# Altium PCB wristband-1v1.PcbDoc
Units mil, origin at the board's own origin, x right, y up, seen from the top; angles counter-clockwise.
Board outline 1555.12 x 610.86 mil, 4 copper layers (Top Layer, Layer 1, Layer 2, Bottom Layer), stack 23.78 mil thick; 50 components, 63 nets, 221 pads, 110 vias.
Unrouted connection lines stored in the file: 30.
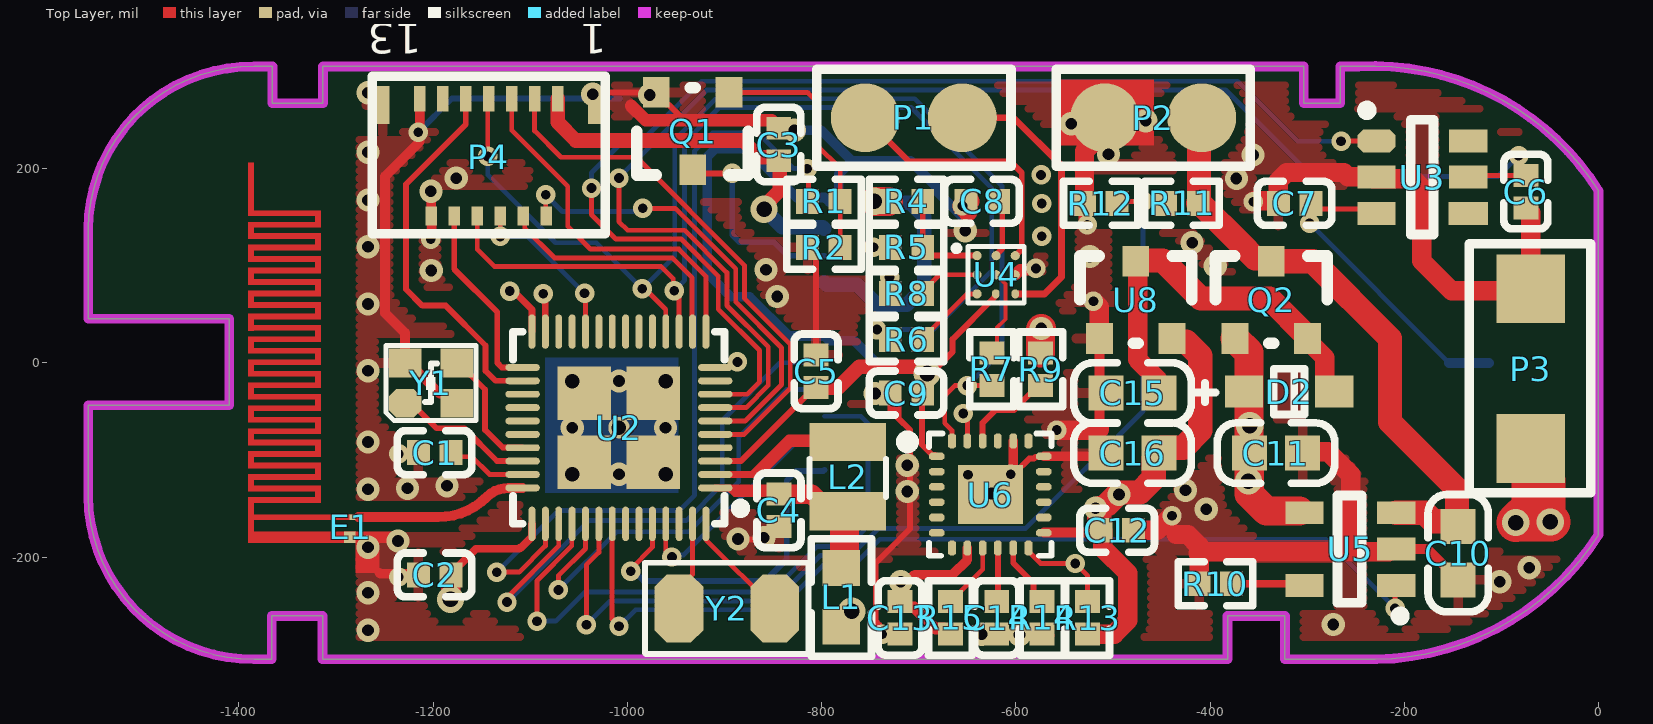
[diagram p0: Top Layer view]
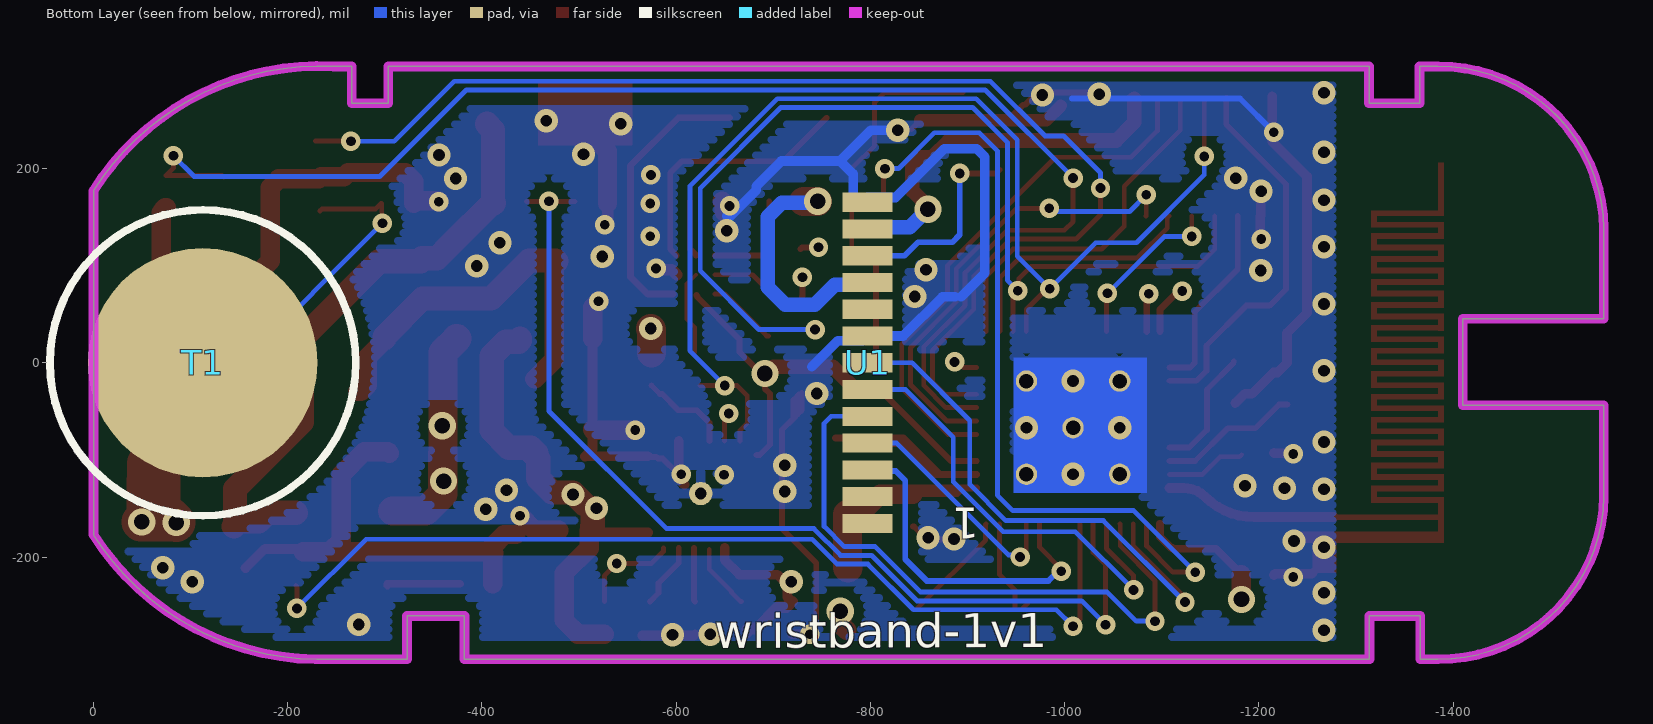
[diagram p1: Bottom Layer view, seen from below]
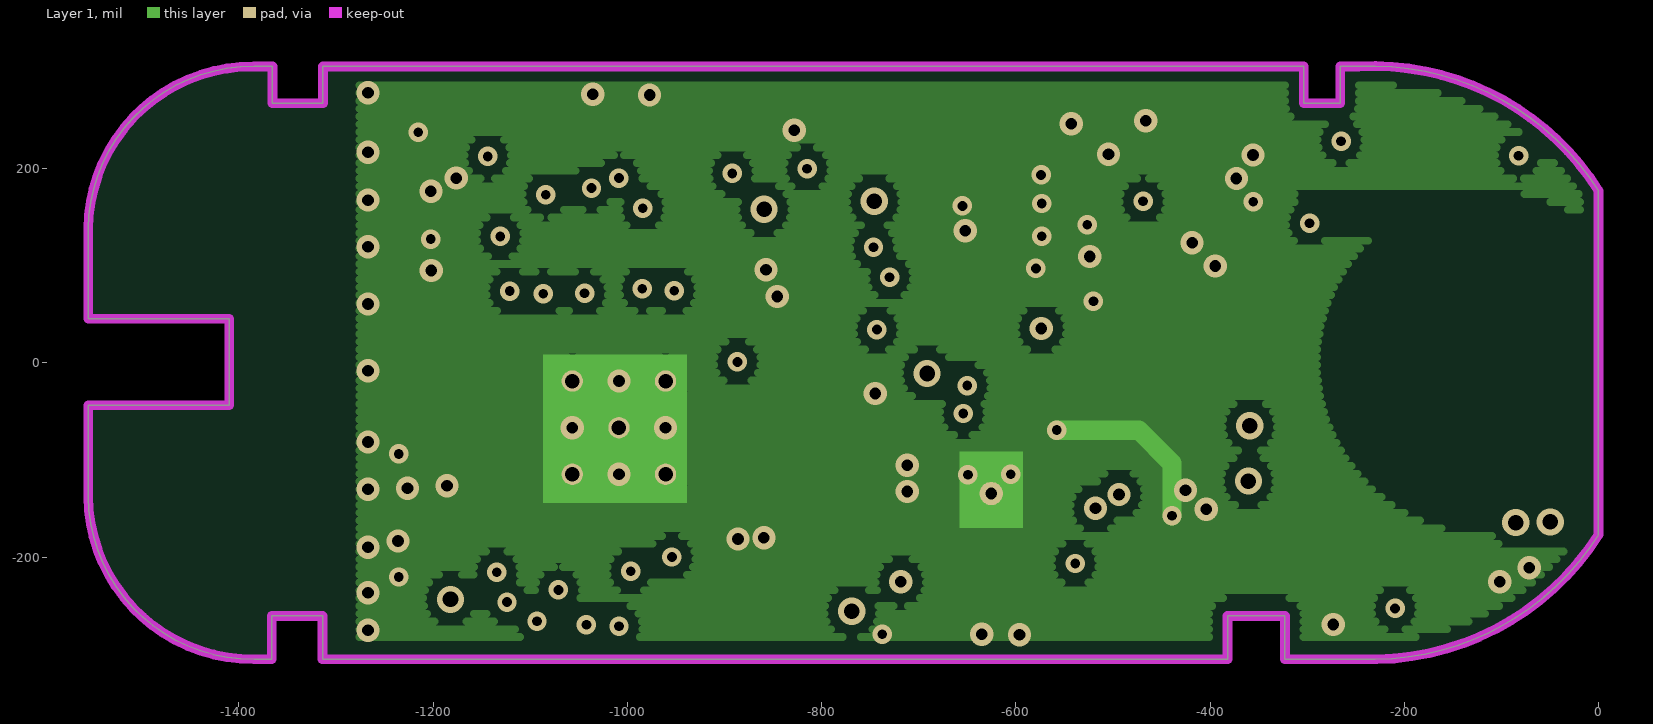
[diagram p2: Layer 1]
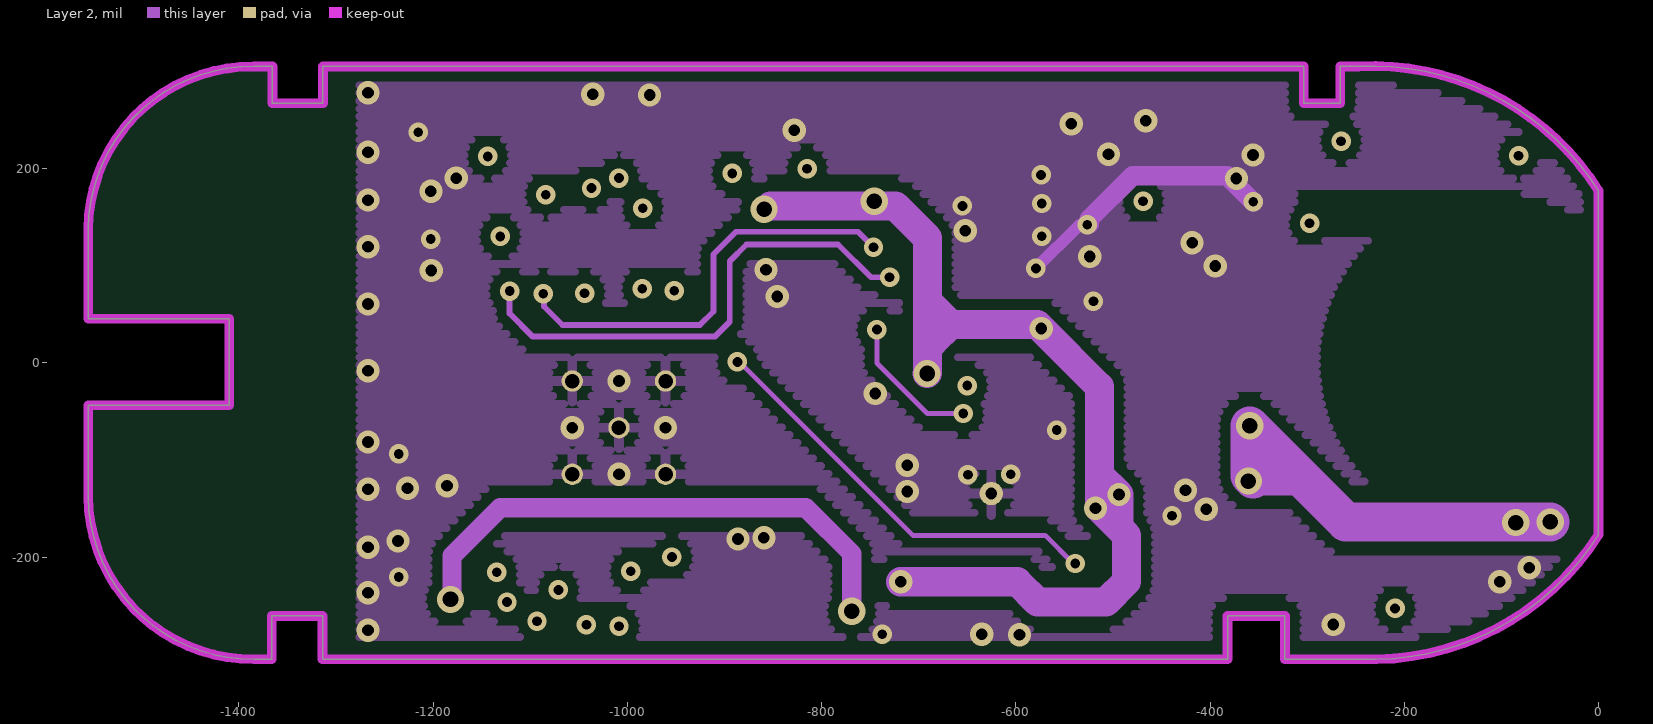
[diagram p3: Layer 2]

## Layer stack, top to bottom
Top Solder: solder mask 0.3937, Solder Resist, Dk 3.5
Top Layer: signal copper 1.4173
Dielectric 2: prepreg 2.7953, PP-006, Dk 4.1
Layer 1: signal copper 1.378
Dielectric 3: prepreg 2.7953, PP-006, Dk 4.1
Layer 2: signal copper 1.378
Dielectric 1: dielectric 12.5984, FR-4, Dk 4.8
Bottom Layer: signal copper 1.4173
Bottom Solder: solder mask 0.3937, Solder Resist, Dk 3.5

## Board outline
-1555.12,-137.8 ccw(c-1386.04,-136.02) -1384.27,-305.1 -1384.27,-305.12 -1366.14,-305.12 -1366.14,-260.71 -1313.78,-260.71 -1313.78,-305.12 -381.89,-305.12 -381.89,-260.71 -322.83,-260.71 -322.83,-305.12 -246.85,-305.12 -246.84,-305.1 ccw(c-233.14,-29.47) 0,-177.15 0,177.17 ccw(c-233.14,29.48) -246.84,305.12 -265.75,305.12 -265.75,267.34 -303.54,267.34 -303.54,305.12 -1313.39,305.12 -1313.39,267.34 -1365.35,267.34 -1365.35,305.12 -1384.27,305.12 ccw(c-1386.03,136.03) -1555.12,137.8 -1555.12,45.28 -1409.98,45.28 -1409.98,-43.7 -1555.12,-43.7

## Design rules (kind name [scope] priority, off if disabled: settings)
Clearance Clearance_2 [InNamedPolygon('GND1')] p1: gap=6 ignorepadtopadclearanceinfootprint=FALSE
Clearance Clearance_1 [InPolygon] p2: gap=10 ignorepadtopadclearanceinfootprint=FALSE
Clearance [All] p3: gap=6 ignorepadtopadclearanceinfootprint=FALSE except(3.5: Arc-SMDPad Track-SMDPad; 4: Arc-Arc Arc-Track Track-Track SMDPad-SMDPad)
ComponentClearance [All] p1 off: gap=10 collisioncheckmode=3 verticalgap=10 showdistances=FALSE
DiffPairsRouting [All] p1: maxlimit=10 minlimit=7 mostfreqgap=8 toplayer_minwidth=6 toplayer_maxwidth=15 toplayer_prefwidth=8 midlayer1_minwidth=6 midlayer1_maxwidth=15 midlayer1_prefwidth=8 midlayer2_minwidth=6 midlayer2_maxwidth=15 midlayer2_prefwidth=8 bottomlayer_minwidth=6 bottomlayer_maxwidth=15 bottomlayer_prefwidth=8 maxuncoupledlength=500
MinimumSolderMaskSliver [All] p1 off: minsoldermaskwidth=10
PolygonConnect PolygonConnect_1 [IsVia] p1: connectstyle=Direct reliefconductorwidth=10 reliefentries=4 polygonreliefangle="90 Angle" airgapwidth=10
PolygonConnect [All] p2: connectstyle=Relief reliefconductorwidth=10 reliefentries=4 polygonreliefangle="90 Angle" airgapwidth=10
RoutingVias [All] p1: holewidth=16 width=28 viastyle="Through Hole" minholewidth=10 minwidth=20 maxholewidth=28 maxwidth=50
SilkToSilkClearance [All] p1 off: silktosilkclearance=10
SilkToSolderMaskClearance [IsPad] p1 off: minsilkscreentomaskgap=10 clearancetoexposedcopper=TRUE
SolderMaskExpansion [All] p1: expansion=4 istentingtop=FALSE
Width [All] p1: maxlimit=100 minlimit=3.5 preferedwidth=10
25 further rules are at their usual default settings.

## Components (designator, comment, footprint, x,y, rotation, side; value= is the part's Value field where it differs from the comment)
C1 "1uF" 0402_C -1181.7,-92.5 r270 top
C2 "0.1uF" 0402_C -1181.7,-218.43 r270 top
C3 "1uF" 0402_C -843.97,208.02 r180 top
C4 "2.2uF" 0402_C -843.81,-168.66 r180 top
C5 "2.2uF" 0402_C -805.63,7.94 r0 top
C6 "NC" 0402_C -74.78,193.01 r0 top
C7 "10pF" 0402_C -296.14,164.16 r270 top
C8 "1uF" 0402_C -651.46,166.26 r90 top
C9 "0.1uF" 0402_C -729.26,-31.15 r90 top
C10 "10uF" 0603_C -144.51,-223.51 r90 top
C11 "10uF" 0603_C -304.56,-93 r180 top
C12 "0.1uF" 0402_C -478.86,-172.36 r270 top
C13 "0.1uF" 0402_C -719.12,-279.37 r180 top
C14 "0.1uF" 0402_C -619.54,-245.9 r0 top
C15 "10uF" 0603_C -452.3,-31.06 r180 top
C16 "10uF" 0603_C -452.3,-93 r180 top
D2 "Diode" SOD-323 -364.97,-29.58 r0 top
E1 "ANTENNA" ANT-F-1-2.4G-0.8 -1283.04,-158.93 r90 top
L1 "0Ω" 0603 -779.61,-211.26 r270 top
L2 "22uH" SMD_2x2mm -772.88,-117.13 r270 top
P1 "0827马达" SIP2-2.54mm#1 -755,252.33 r90 top
P2 "锂电池（圆形焊盘）" SIP2-2.54mm#1 -408.43,252.33 r270 top
P3 "电源(矩形焊盘)" SIP2-2.54mm#2 -55.59,-51.12 r180 top
P4 "FPC连接器 13PIN_0.3mm" FFC/FPC-13(6+7)-P0.3 -1142.66,271.98 r180 top
Q1 "QNPN" SOT-23 -895.29,278.38 r180 top
Q2 "MOSFET-P" SOT-23 -374.38,24.97 r0 top
R1 "1K" 0402 -780.77,166.26 r180 top
R2 "10K" 0402 -780.77,118.84 r180 top
R4 "0R" 0402 -729.26,166.26 r0 top
R5 "10K" 0402 -729.26,118.84 r0 top
R6 "0R" 0402 -729.26,24.01 r0 top
R7 "0R" 0402 -624.61,-23.41 r90 top
R8 "0R" 0402 -729.26,71.43 r0 top
R9 "10K" 0402 -574.41,-23.41 r90 top
R10 "100K" 0402 -377.71,-227.48 r180 top
R11 "100K" 0402 -412.1,164.16 r180 top
R12 "100K" 0402 -529.23,164.16 r0 top
R13 "10K" 0402 -526.08,-245.9 r270 top
R14 "10K" 0402 -572.81,-245.9 r270 top
R15 "10K" 0402 -667.27,-245.9 r270 top
T1 "PAD" TESTPOINT1 -112.59,0 r180 bottom
U1 "096_IPS显示屏" FFC-13-P0.7 -797.04,-165.35 r90 bottom locked
U2 "CH583M" QFN48_5X5 -1008.59,-66.8 r90 top
U3 "TPP223-BA6" SOT-23-6 -228.62,228.48 r270 top
U4 "DRV2605YZFR" DSBGA-9-P0.5-H0.625mm -620.22,90.63 r0 top
U5 "TP4054" SOT-23-5 -208.18,-229.21 r90 top
U6 "MPU9250" QFN24-3.0X3.0X1.0 -626.24,-135.67 r0 top
U8 "6219P33M" SOT-23 -513.88,24.97 r0 top
Y1 "32MHz" XT2016 -1228.85,-41.5 r0 top
Y2 "32.768K" fc-135 -848.35,-252.89 r180 top

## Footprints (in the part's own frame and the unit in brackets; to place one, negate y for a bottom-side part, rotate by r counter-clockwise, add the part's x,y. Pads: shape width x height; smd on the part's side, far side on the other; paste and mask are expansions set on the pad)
0402 [mm]
  rect 0.6x0.65 smd mask+0.051: 1(0,0) 2(0.85,0)
  silkscreen extent -0.55,-0.58 1.4,0.57
0402_C [mm]
  rect 0.65x0.6 smd mask+0.051: 1(0,0) 2(0,-0.85)
  silkscreen extent -0.58,-1.4 0.57,0.55
0603 [mm]
  rect 0.93x0.98 smd: 1(0,0) 2(1.54,0)
  silkscreen extent -0.76,-0.79 2.3,0.79
0603_C [mil]
  rect 36x36 smd: 1(0,0) 2(55,0)
  silkscreen extent -33,-31 88,31
ANT-F-1-2.4G-0.8 [mm]
  rect 0.3x0.3 smd mask+0: 0(-0.525,0.075)
  rect 0.15x0.15 smd mask+0: 1(0,0)
  Top Layer region: 7.875,0.825 8.025,0.825 8.025,2.725 7.875,2.725
  Top Layer region: 7.875,2.575 9.275,2.575 9.275,2.725 7.875,2.725
  Top Layer region: 7.575,0.825 8.025,0.825 8.025,0.975 7.575,0.975
  Top Layer region: 6.675,0.825 6.825,0.825 6.825,2.725 6.675,2.725
  Top Layer region: 6.975,0.825 7.125,0.825 7.125,2.725 6.975,2.725
  Top Layer region: 7.275,0.825 7.425,0.825 7.425,2.725 7.275,2.725
  Top Layer region: 7.575,0.825 7.725,0.825 7.725,2.725 7.575,2.725
  Top Layer region: 6.675,2.575 7.125,2.575 7.125,2.725 6.675,2.725
  Top Layer region: 7.275,2.575 7.725,2.575 7.725,2.725 7.275,2.725
  Top Layer region: 6.375,0.825 6.825,0.825 6.825,0.975 6.375,0.975
  Top Layer region: 6.975,0.825 7.425,0.825 7.425,0.975 6.975,0.975
  Top Layer region: 5.475,0.825 5.625,0.825 5.625,2.725 5.475,2.725
  Top Layer region: 5.775,0.825 5.925,0.825 5.925,2.725 5.775,2.725
  Top Layer region: 6.075,0.825 6.225,0.825 6.225,2.725 6.075,2.725
  Top Layer region: 6.375,0.825 6.525,0.825 6.525,2.725 6.375,2.725
  Top Layer region: 5.475,2.575 5.925,2.575 5.925,2.725 5.475,2.725
  Top Layer region: 6.075,2.575 6.525,2.575 6.525,2.725 6.075,2.725
  Top Layer region: 5.175,0.825 5.625,0.825 5.625,0.975 5.175,0.975
  Top Layer region: 5.775,0.825 6.225,0.825 6.225,0.975 5.775,0.975
  Top Layer region: 4.275,0.825 4.425,0.825 4.425,2.725 4.275,2.725
  Top Layer region: 4.575,0.825 4.725,0.825 4.725,2.725 4.575,2.725
  Top Layer region: 4.875,0.825 5.025,0.825 5.025,2.725 4.875,2.725
  Top Layer region: 5.175,0.825 5.325,0.825 5.325,2.725 5.175,2.725
  Top Layer region: 4.275,2.575 4.725,2.575 4.725,2.725 4.275,2.725
  Top Layer region: 4.875,2.575 5.325,2.575 5.325,2.725 4.875,2.725
  Top Layer region: 3.975,0.825 4.425,0.825 4.425,0.975 3.975,0.975
  Top Layer region: 4.575,0.825 5.025,0.825 5.025,0.975 4.575,0.975
  Top Layer region: 3.075,0.825 3.225,0.825 3.225,2.725 3.075,2.725
  Top Layer region: 3.375,0.825 3.525,0.825 3.525,2.725 3.375,2.725
  Top Layer region: 3.675,0.825 3.825,0.825 3.825,2.725 3.675,2.725
  Top Layer region: 3.975,0.825 4.125,0.825 4.125,2.725 3.975,2.725
  Top Layer region: 3.075,2.575 3.525,2.575 3.525,2.725 3.075,2.725
  Top Layer region: 3.675,2.575 4.125,2.575 4.125,2.725 3.675,2.725
  Top Layer region: 2.775,0.825 3.225,0.825 3.225,0.975 2.775,0.975
  Top Layer region: 3.375,0.825 3.825,0.825 3.825,0.975 3.375,0.975
  Top Layer region: 1.875,0.825 2.025,0.825 2.025,2.725 1.875,2.725
  Top Layer region: 2.175,0.825 2.325,0.825 2.325,2.725 2.175,2.725
  Top Layer region: 2.475,0.825 2.625,0.825 2.625,2.725 2.475,2.725
  Top Layer region: 2.775,0.825 2.925,0.825 2.925,2.725 2.775,2.725
  Top Layer region: 1.875,2.575 2.325,2.575 2.325,2.725 1.875,2.725
  Top Layer region: 2.475,2.575 2.925,2.575 2.925,2.725 2.475,2.725
  Top Layer region: 1.575,0.825 2.025,0.825 2.025,0.975 1.575,0.975
  Top Layer region: 2.175,0.825 2.625,0.825 2.625,0.975 2.175,0.975
  Top Layer region: 0.975,0.825 1.425,0.825 1.425,0.975 0.975,0.975
  Top Layer region: 0.375,0.825 0.825,0.825 0.825,0.975 0.375,0.975
  Top Layer region: 1.275,2.575 1.725,2.575 1.725,2.725 1.275,2.725
  Top Layer region: 0.675,2.575 1.125,2.575 1.125,2.725 0.675,2.725
  Top Layer region: 0.075,2.575 0.525,2.575 0.525,2.725 0.075,2.725
  Top Layer region: 1.575,0.825 1.725,0.825 1.725,2.725 1.575,2.725
  Top Layer region: 1.275,0.825 1.425,0.825 1.425,2.725 1.275,2.725
  Top Layer region: 0.975,0.825 1.125,0.825 1.125,2.725 0.975,2.725
  Top Layer region: 0.675,0.825 0.825,0.825 0.825,2.725 0.675,2.725
  Top Layer region: 0.375,0.825 0.525,0.825 0.525,2.725 0.375,2.725
  Top Layer region: 0.075,2.575 0.075,2.725 -0.675,2.725 -0.675,2.575
  Top Layer region: -0.075,-0.075 0.075,-0.075 0.075,2.725 -0.075,2.725
  Top Layer region: -0.675,-0.075 -0.375,-0.075 -0.375,2.725 -0.675,2.725
DSBGA-9-P0.5-H0.625mm [mm]
  round 0.24 smd: A1(-0.5,0.5) A2(0,0.5) A3(0.5,0.5) B1(-0.5,0) B2(0,0) B3(0.5,0) C1(-0.5,-0.5)
  oval 0.203x0.24 smd: C2(-0.008,-0.5) C3(0.5,-0.5)
  silkscreen extent -1.11,-0.74 0.74,0.77
fc-135 [mil]
  oct 50x70 smd: 1(0,0) 2(98.43,0)
  silkscreen extent -35,-47 133,47
FFC-13-P0.7 [mm]
  rect 0.5x1.3 smd: 1(0,0) 2(0.7,0) 3(1.4,0) 4(2.1,0) 5(2.8,0) 6(3.5,0) 7(4.2,0) 8(4.9,0) 9(5.6,0) 10(6.3,0) 11(7,0) 12(7.7,0) 13(8.4,0)
FFC/FPC-13(6+7)-P0.3 [mm]
  rect 0.35x1 smd mask+0.102: 0(-2.775,0.165) 0(2.775,0.165)
  rect 0.3x0.67 smd mask+0.102: 1(-1.8,0) 3(-1.2,0) 5(-0.6,0) 7(0,0) 9(0.6,0) 11(1.2,0) 13(1.8,0)
  rect 0.3x0.5 smd mask+0.102: 2(-1.5,3.065) 4(-0.9,3.065) 6(-0.3,3.065) 8(0.3,3.065) 10(0.9,3.065) 12(1.5,3.065)
  silkscreen extent -3.05,-0.59 3.05,3.53
QFN24-3.0X3.0X1.0 [mm]
  oct 0.4x0.2 smd mask+0.102: 1(-1.4,1) 2(-1.4,0.6) 3(-1.4,0.2) 4(-1.4,-0.2) 5(-1.4,-0.6) 6(-1.4,-1) 13(1.4,-1) 14(1.4,-0.6) 15(1.4,-0.2) 16(1.4,0.2) 17(1.4,0.6) 18(1.4,1)
  oct 0.2x0.4 smd mask+0.102: 7(-1,-1.4) 8(-0.6,-1.4) 9(-0.2,-1.4) 10(0.2,-1.4) 11(0.6,-1.4) 12(1,-1.4) 19(1,1.4) 20(0.6,1.4) 21(0.2,1.4) 22(-0.2,1.4) 23(-0.6,1.4) 24(-1,1.4)
  rect 1.7x1.54 smd mask+0.102: 25(0,0)
  silkscreen extent -2.31,-1.6 1.6,1.6
QFN48_5X5 [mm]
  round 0.559 hole 0.381 mask+0.102: 0(-1.219,-1.219) 0(-1.219,1.219) 0(0,0) 0(1.219,-1.219) 0(1.219,1.219)
  rect 1.397x1.397 smd mask+0: 0(-0.901,-0.895) 0(-0.901,0.908) 0(0.902,-0.895) 0(0.902,0.908)
  oval 0.18x0.9 smd: 1(-1.575,-2.519) 2(-1.225,-2.519) 3(-0.875,-2.519) 4(-0.525,-2.519) 5(-0.175,-2.519) 6(0.175,-2.519) 7(0.525,-2.519) 8(0.875,-2.519) 9(1.225,-2.519) 10(1.575,-2.519) 25(1.575,2.519) 26(1.225,2.519) 27(0.875,2.519) 28(0.525,2.519) 29(0.175,2.519) 30(-0.175,2.519) 31(-0.525,2.519) 32(-0.875,2.519) 33(-1.225,2.519) 34(-1.575,2.519)
  oval 0.9x0.18 smd: 11(2.514,-2.275) 12(2.514,-1.925) 13(2.514,-1.575) 14(2.514,-1.225) 15(2.514,-0.875) 16(2.514,-0.525) 17(2.514,-0.175) 18(2.514,0.175) 19(2.514,0.525) 20(2.514,0.875) 21(2.514,1.225) 22(2.514,1.575) 23(2.514,1.925) 24(2.514,2.275) 35(-2.514,2.275) 36(-2.514,1.925) 37(-2.514,1.575) 38(-2.514,1.225) 39(-2.514,0.875) 40(-2.514,0.525) 41(-2.514,0.175) 42(-2.514,-0.175) 43(-2.514,-0.525) 44(-2.514,-0.875) 45(-2.514,-1.225) 46(-2.514,-1.575) 47(-2.514,-1.925) 48(-2.514,-2.275)
  silkscreen extent -2.51,-3.31 2.51,2.77
SIP2-2.54mm#1 [mm]
  round 1.8 smd: 1(0,0) 2(0,-2.54)
  silkscreen extent -1.27,-3.81 1.27,1.27
SIP2-2.54mm#2 [mm]
  rect 1.8x1.8 smd: 1(0.361,0.94) 2(0.361,-3.234)
  silkscreen extent -1.21,-4.42 1.97,2.1
SMD_2x2mm [mm]
  rect 1x2 smd: 1(-0.905,0) 2(0.905,0)
  silkscreen extent -0.47,-1 0.53,1
SOD-323 [mm]
  rect 1x0.83 smd: 1(0,0) 2(2.36,0)
  silkscreen extent -1.28,-0.6 1.58,0.6
SOT-23 [mm]
  rect 0.7x0.8 smd: 1(0,0) 2(1.9,0) 3(0.95,2.02)
  silkscreen extent -0.51,-0.13 2.41,2.16
SOT-23-5 [mm]
  rect 0.6x1 smd: 1(0,0) 2(0.95,0) 3(1.9,0) 4(1.9,2.4) 5(0,2.4)
  silkscreen extent -0.92,-0.23 2.35,1.54
SOT-23-6 [mm] "SOT-23-6"
  oct 0.6x1 smd: 1(0,0)
  rect 0.6x1 smd: 2(0.95,0) 3(1.9,0) 5(0.95,2.4) 6(0,2.4)
  rect 0.6x1.04 smd: 4(1.9,2.4)
  silkscreen extent -0.93,-0.38 2.45,1.49
TESTPOINT1 [mm]
  round 6 smd: 1(0,0)
  silkscreen extent -4,-4 4,4
XT2016 [mm]
  oct 0.85x0.75 smd: 1(0,0)
  rect 0.85x0.75 smd: 2(1.35,0) 3(1.35,1.05) 4(0,1.05)
  silkscreen extent -0.5,-0.45 1.85,1.5

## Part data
C1 C2 C4 C5 C8 C9 C12 C13 C14: library part CAP, "Capacitor"
C3 C6 C7 C10 C11 C15 C16: library part Cap, "Capacitor"
D2: "Default Diode"
E1: "Generic Antenna"
L1 L2: library part INDUCTOR
P1: library part "Header 2H", "Header, 2-Pin, Right Angle"
P2 P3: library part "Header 2", "Header, 2-Pin"
P4: library part "Header 13", "Header, 13-Pin"
Q1: "NPN Bipolar Transistor"
Q2: "P-Channel MOSFET"
R1 R2 R4 R5 R6 R7 R8 R9 R10 R11 R12 R13 R14 R15: library part Res1, "Resistor"
U1: library part Component_1
U2: "RISC-V MCU with BLE/2*USB/ADC/PWM/SPI/I2C/4*UART"
U4: "No Description Available"
U6: library part PMU9250
Y1: library part 晶体
Y2: library part XTAL, "Crystal Oscillator"

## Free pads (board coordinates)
  round 24 hole 12 mask+4: ""(-625.21,-134.61)

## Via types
v1: diameter 24, hole 12, Top Layer to Bottom Layer, tented both sides, 51 vias
v2: diameter 20, hole 10, Top Layer to Bottom Layer, tented both sides, 50 vias
v3: diameter 28, hole 16, Top Layer to Bottom Layer, tented both sides, 9 vias

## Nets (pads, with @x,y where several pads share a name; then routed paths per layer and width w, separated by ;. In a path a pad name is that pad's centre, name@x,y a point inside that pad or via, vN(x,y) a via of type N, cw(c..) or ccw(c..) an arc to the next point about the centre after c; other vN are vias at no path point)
+3V3: C3.1 C5.2 C9.2 C12.2 C13.2 C16.1 P4.1 R4.1 R9.2 R13.2 R15.2 U1.10 U1.12 U2.3 U4.C2 U6.1 U6.8 U6.13 U8.2 | length 2885.9
  Top Layer w6: U2.3 -883.13,-101.25 -816.22,-34.34 -815.42,-34.34 C5.2@-806.63,-25.54 ; v3(-691.27,-11.01) -691.27,-26.63 C9.2 -696.53,-31.88 -696.53,-84.36 -685.93,-94.96 U6.1@-682.51,-94.96 ; v3@-682.45,-6.2 -664.98,11.27 -664.98,24.37 -621.8,67.54 -621.8,68.39 -620.9,69.29 U4.C2@-620.9,69.94
  Top Layer w10: C13.2 -714.39,-241.17 -714.39,-228.49 -704.13,-218.22 -665.22,-218.22 -649.86,-202.87 U6.8 ; U6.13 -570.86,-174.78 -514.84,-174.78 C12.2@-513.75,-175.87
  Top Layer w12: C13.2 -713.31,-251.71 -704.47,-251.71 -682.63,-273.56 -674.06,-273.56 -673.08,-274.54 R15.2@-673.08,-277.12
  Top Layer w15: P4.1 -1071.79,247.67 -1053.03,228.91 -880.86,228.91 -863.63,211.68 -849.27,211.68 -845.76,208.17 C3.1@-845.76,205.26 ; v3(-859.19,158.08) -859.19,161.12 -842.91,177.4 -842.91,206.95 C3.1 ; C5.2 -782.97,-25.53 -761.31,-3.86 v3@-699.77,-3.86
  Top Layer w20: R13.2 -498.78,-279.37 -484.67,-265.26 -484.67,-216.59 -510.51,-190.76 -510.51,-172.99 C12.2@-512.49,-171.01
  Top Layer w25: v1@-513.94,-149.78 -513.94,-168.01 C12.2@-513.49,-168.46 ; -505.91,-145.85 -493.57,-133.51 -472.45,-133.51 -457.8,-118.87 -457.8,-98.5 C16.1 ; C16.1@-455.75,-92.96 -450.29,-87.5 -427.68,-87.5 -409.9,-69.72 -409.9,7.27 -424.35,21.72 -437.79,21.72 -439.07,23 U8.2
  Top Layer w30: v3@-745.42,166.07 v3@-745.22,166.26 ; v3@-744.22,166.26 R4.1@-731.29,166.26 ; R9.2 -574.41,34.22 -573.74,34.89 v1(-573.74,35.26)
  Layer 2 w30: v3@-852.69,161.49 -723.81,161.49 -690.94,128.61 -690.94,39.39 ; v1(-718.48,-225.38) -598.43,-225.38 -577.51,-246.29 -507.1,-246.29 -485.82,-225.01 -485.82,-177.89 -493.74,-169.97 ; v3(-691.27,-11.01) -690.94,-10.68 -690.94,39.39 ; -688.19,60.45 -667.13,39.39 ; -685.87,20.65 -667.13,39.39 ; -690.94,39.39 -667.13,39.39 ; -667.13,39.39 -577.87,39.39 v1(-573.74,35.26) -513.94,-24.54 -513.94,-115.49 ; -513.94,-115.49 -513.94,-149.78 -493.74,-169.97 ; -513.94,-115.49 v1(-493.74,-135.68) -493.74,-169.97
  Bottom Layer w15: v3(-859.19,158.08) -840.57,139.46 -798.7,139.46 U1.12 ; U1.10 -794.77,80.41 -763.1,80.41 -742.61,59.91 -712.39,59.91 -694.3,78.01 -694.3,150.29 -708.59,164.58 -744.92,164.58 v3@-746.64,166.3
  other v1: -517.94,-149.78
  other v3: -745.64,166.3
+5V: C15.1 D2.2 Q2.2 U8.3 | length 410.5
  Top Layer w20: U8.3 -474.51,102.54 -474.51,3.54 C15.1@-454.27,-16.7 ; Q2.2@-301.4,24.83 -281.74,5.17 -281.74,-23.24 -275.4,-29.58 D2.2
  Top Layer w25: U8.3 -475.72,105.25 -448.68,105.25 -409.62,66.2 -338.83,66.2 -299.57,26.94 Q2.2
ANT: E1.1 U2.34 | length 177.1
  Top Layer w10.3: -1276.78,-158.93 -1194.97,-158.93 ccw(c-1194.97,-87.58) -1144.52,-138.03 cw(c-1122.25,-160.3) -1122.25,-128.81 U2.34
BLK: R1.2 U2.36 | length 848.6
  Top Layer w5: v2(-1134.42,-215.56) -1111.43,-215.56 -1084.37,-188.49 U2.36 ; v2(-814.91,199.89) -813.42,198.39 -813.42,167.07 R1.2
  Bottom Layer w5: v2(-1134.42,-215.56) -1071.04,-152.17 -946.44,-152.17 -930.7,-136.43 -930.7,218.34 -912.18,236.87 -865.87,236.87 -828.9,199.89 v2(-814.91,199.89)
BOOT: P4.9 U2.26 | length 396.3
  Top Layer w6: P4.9 -1166.28,245.4 -1227.88,183.8 -1227.88,75.74 -1210.99,58.85 -1186.95,58.85 -1146.01,17.92 -1146.01,-8.32 -1135.77,-18.57 U2.26
CS: U1.7 U2.37 | length 570.1
  Top Layer w5: v2(-1123.83,-246.41) -1123.83,-241.73 -1070.59,-188.49 U2.37
  Bottom Layer w5: v2(-1123.83,-246.41) -1039.87,-162.44 -939.45,-162.44 -902.24,-125.23 -902.24,-59.42 -842.82,0.01 U1.7
DC: U1.5 U2.38 | length 650.3
  Top Layer w5: v2(-1093,-266) -1093,-224.38 -1057.11,-188.49 -1057.11,-166.07 U2.38
  Bottom Layer w5: v2(-1093,-266) -1073.69,-266 -1043.77,-236.09 -851.6,-236.09 -804.77,-189.25 -773.04,-189.25 -752.21,-168.43 -752.21,-62.39 -759.49,-55.11 U1.5
DRV_EN: R5.1 U2.23 | length 500.2
  Top Layer w6: v2(-746.46,118.86) -729.77,118.86 R5.1@-728.07,117.15
  Top Layer w7: v2(-1086.51,70.96) -1084.39,68.84 U2.23@-1084.39,32.19
  Layer 2 w6: v2(-1086.51,70.96) -1085.85,70.3 -1085.85,57.99 -1066.66,38.8 -925.3,38.8 -911.26,52.84 -911.26,111.65 -888.03,134.89 -762.49,134.89 v2(-746.46,118.86)
DRV_PWM: R8.1 U2.24 | length 587.7
  Top Layer w6: v2(-729.92,88.07) -729.92,68.41 R8.1@-729.58,68.07
  Top Layer w7: v2(-1121.13,73.84) -1116.97,73.84 -1098.15,55.03 U2.24
  Layer 2 w6: v2(-1121.13,73.84) -1121.13,50.8 -1097.27,26.94 -909.96,26.94 -894.56,42.34 -894.56,104.56 -877.2,121.91 -782.93,121.91 -749.09,88.07 v2(-729.92,88.07)
DRV_SCL: P4.8 R6.1 U2.13 U6.23 | length 1228
  Top Layer w5: P4.8 -1154.47,116.78 -1136.68,98.99 -964.97,98.99 -952.72,86.75 -952.72,75.23 v2(-951.7,74.2) ; v2@-946.75,72.01 -946.75,32.35 U2.13 ; v2(-653.98,-52.25) -649.85,-56.37 U6.23
  Layer 2 w5: v2(-742.92,34.21) -742.92,-0.45 -691.13,-52.25 v2(-653.98,-52.25)
  Bottom Layer w5: v2(-951.7,74.2) -940.95,84.95 -940.95,227.15 -905.25,262.86 -707.68,262.86 -624.66,179.84 -624.66,94.75 -685.2,34.21 v2(-742.92,34.21)
DRV_SDA: P4.7 R7.1 U2.14 U6.24 | length 1222.2
  Top Layer w5: v2(-1143.72,212.48) -1143.72,270.92 P4.7 ; v2(-984.5,76.34) -981.8,76.34 -960.36,54.89 U2.14 ; U6.24 -665.61,-69.78 -673.17,-62.22 -673.17,-33.8 -662.8,-23.42 R7.1
  Bottom Layer w5: v2(-1143.72,212.48) -1143.72,193.5 -1073.89,123.67 -1031.84,123.67 v2(-984.5,76.34) ; v2@-982.98,77.86 -951.16,109.68 -951.16,229.68 -908.97,271.86 -703.95,271.86 -614.07,181.98 -614.07,12.39 v2(-649.88,-23.42)
GND: C1.2 C2.2 C3.2 C4.1 C5.1 C6.2 C7.2 C8.1 C9.1 C10.1 C11.1 C12.1 C13.1 C14.2 C15.2 C16.2 E1.0 P2.2 P3.2 P4.0 P4.12 P4.13 pad. Q1.2 R2.2 R10.2 R12.1 R14.2 U1.8 U1.13 U2.0 U3.2 U4.B3 U5.2 U6.18 U6.20 U6.25 U8.1 Y1.2 Y1.4 | length 4284.7
  Top Layer w6: P4.0@-1033.4,274.49 -1029.51,278.38 Q1.2 ; Q1.2@-970.09,276.41 -959.31,265.63 -957.34,265.63 -941.36,249.65 ; v1@-893.95,-181.9 -857.05,-181.9 -853.6,-178.45 -853.6,-177.47 -844.79,-168.66 C4.1 ; C3.2@-851.33,249.65 C3.2@-842.26,240.57 ; R2.2@-815.6,117.47 -814.05,117.47 -805.63,109.05 C5.1 ; C9.1 -729.26,-48.78 -724.85,-53.19 ; C9.1@-726.27,-32.76 C9.1@-724.85,-34.18 ; C13.1 -719.36,-279.6 -731.04,-279.6 -734.08,-276.56 -734.08,-276.18 -737.15,-276.18 -740.19,-273.14 -740.19,-270.07 -744.1,-266.15 -744.1,-206.05 -708.97,-170.92 -708.97,-69.07 -720.45,-57.59 ; U6.25@-600.17,-115.09 -600.17,-112.74 -586.12,-98.7 -581.44,-98.7 -579.77,-97.03 -571.85,-97.03 U6.18 ; -724.85,-53.19 -720.45,-57.59 ; -724.85,-53.19 C9.1@-724.85,-34.18 ; C9.1@-724.85,-34.18 -720.45,-38.58 -720.45,-57.59
  Top Layer w10: -1255.27,-216.23 -1254.17,-217.33 -1216.27,-217.33 C2.2 ; v2(-1235.42,-93.82) -1234.77,-93.16 -1215.83,-93.16 C1.2 ; v2@-1213.61,227.76 -1249.38,191.99 -1249.38,51.35 -1228.85,30.82 Y1.4 -1219.09,-9.93 -1214.98,-9.93 -1193.17,-31.74 -1185.47,-31.74 Y1.2 ; v2@-1213.61,237.32 P4.13@-1213.61,274.31 ; v1@-1203.19,175.76 -1201.71,174.28 P4.12 -1201.41,151.01 -1201.41,128.46 v2(-1202.46,127.41) ; v2(-737.51,-279.6) -718.88,-279.6 C13.1 ; C14.2 -618.12,-280.79 R14.2@-564.97,-280.79 ; U6.25@-608.56,-125.67 -602.62,-119.74 U6.20 ; U6.18 C16.2@-507.87,-96.3 ; U8.1 -513.88,-68.45 -513.88,-88.73 C16.2@-506.15,-96.46 ; U5.2 -176.22,-191.81 -156.66,-211.36 C10.1@-156.4,-211.36
  Top Layer w12: U4.B3 -595.52,95.64 -580.75,95.64 v2(-579.22,97.17) ; R12.1 -529.46,163.93 -529.46,144.77 v2@-526.78,142.09
  Top Layer w13: -995.97,264.69 -980.93,249.65 -941.36,249.65 C3.2@-851.33,249.65
  Top Layer w20: v2(-654.91,161.55) -654.91,161.13 -649.27,155.49 -649.27,164.45 C8.1@-647.46,166.26 ; v2(-557.76,-69.3) -514.72,-69.3 -513.88,-68.45 ; R12.1 -529.23,217.76 -505.14,241.86 P2.2@-505.14,246.32 ; v2(-520.02,63.36) -513.88,57.22 U8.1 ; C12.1 -454.13,-172.36 v2(-439.13,-157.36) ; -434.72,-176.77 -422.89,-176.77 -411.17,-188.49 -411.17,-195.25 ; -412.02,-196.1 -411.17,-195.25 ; R10.2 -411.17,-195.25 ; v2(-355.41,165.69) -354.16,166.95 -331.41,166.95 -329.6,165.14 C7.2 ; C7.2@-329.74,166.95 -329.74,187.19 -320.96,195.97 -262.38,195.97 -257.94,191.54 -234.27,191.54 -232.03,189.3 -190.72,189.3 -181.94,180.52 -181.94,104.91 -151.25,74.22 -71.79,74.22 P3.2 ; C11.1 -303.03,-91.47 -278.81,-91.47 -255.28,-115 -255.28,-182.71 -243.56,-194.42 ; U5.2@-215.78,-194.42 -243.56,-194.42 ; C6.2 -73.8,159.54 -71.98,157.73 -71.98,156.75 -69.56,154.32 P3.2@-69.56,74.22 ; -411.17,-195.25 -410.34,-194.42 -243.56,-194.42
  Layer 2 w12: v2(-579.22,97.17) -534.31,142.09 v2(-526.25,142.09)
  Layer 2 w20: v2@-524.31,143.21 -524.31,147.88 -479.71,192.47 -382.19,192.47 v2(-355.41,165.69)
  Layer 1 w20: v2(-557.76,-69.3) -473.34,-69.3 -439.13,-103.51 v2(-439.13,-157.36)
  Bottom Layer w6: v2(-1215.23,237.32) -1180.4,272.16 -1007.52,272.16
  Bottom Layer w10: -893.23,67.88 -917.71,92.36 -917.71,212.09 -909.31,220.49 -876.01,220.49 -825.72,170.2 -796.85,170.2 -792,165.36 -786.97,165.36 -782.12,170.2 -782.12,194.41 -768.83,207.71 ; -887.03,67.88 -874.02,67.88 -833.7,27.57 U1.8 -792.2,22.72 -766.35,22.72 -739.59,-4.03 ; v1(-828.12,239.49) -800.61,239.49 -768.83,207.71 ; -652.26,151.13 -655.73,151.13 -682.41,177.81 -682.41,181.89 -708.23,207.71 -768.83,207.71
  other v1: -596.08,-280.01 -635.18,-279.48 -1267.05,-275.3 -273.2,-269.43 -1267.05,-236.72 -101.77,-225.31 -71.39,-210.89 -1267.05,-190.02 -1236.13,-183.47 -885.95,-181.37 -859.33,-180.18 -403.91,-150.86 -711.77,-132.53 -425.24,-131.37 -1267.05,-130.14 -1226.31,-129.32 -1185.71,-126.76 -1008.59,-114.8 -711.77,-105.45 -1267.05,-81.58 -1056.59,-66.8 -960.59,-66.8 -744.77,-31.59 -1008.59,-18.8 -1267.05,-8.11 -1267.05,60.51 -845.67,68.32 -1202,95 -857.24,95.71 -394.44,99.69 -523.72,109.46 -1267.05,119.51 -418.44,123.69 -652.14,135.89 -1267.05,167.53 -1202.19,176.76 -372.81,189.72 -1176.16,190.19 -355.67,213.97 -504.55,214.87 -1267.05,216.82 -542.93,246.25 -466.17,249.2 -977.03,275.8 -1035.4,276.49 -1267.05,278.08
  other v2: -1235.3,-220.53 -649.22,-115.32 -605.17,-114.74 -573.17,130.38 -573.17,164.01 -573.96,193.48
INT: R13.1 U2.10 U6.12 | length 560.2
  Top Layer w5: U2.10 -895.82,-4.79 -894.21,-3.18 -894.21,-2.84 -890.49,0.88 v2(-886.62,0.88) ; U6.12 -586.87,-194.22 -574.45,-206.64 v2(-538.86,-206.64) -526.08,-219.42 R13.1
  Layer 2 w5: v2(-886.62,0.88) -884.53,0.88 -705.94,-177.71 -569.61,-177.71 -540.68,-206.64 v2(-538.86,-206.64)
IO: U2.41 U5.1 | length 998.7
  Top Layer w5: U2.41 -1015.88,-166.17 -1015.88,-264 v2(-1008.52,-271.35) ; v2(-209.44,-252.89) -209.44,-230.47 U5.1
  Bottom Layer w5: v2(-1008.52,-271.35) -991.45,-254.27 -844.33,-254.27 -797.31,-207.25 -765.59,-207.25 -740,-181.67 -280.66,-181.67 v2(-209.44,-252.89)
IO_ADC: R11.2 R12.2 U2.40 | length 1039.7
  Top Layer w5: v2(-1042.06,-269.64) -1042.06,-208.03 -1029.26,-195.23 U2.40 ; R12.2@-495.77,166.26 R11.2@-445.56,166.26
  Bottom Layer w5: v2(-1042.06,-269.64) -1017.5,-245.09 -847.87,-245.09 -801.04,-198.25 -769.31,-198.25 -741.79,-170.73 -590.03,-170.73 -468.94,-49.64 v2(-468.94,166.47)
ISP_SCL: U1.4 U2.45 | length 242.4
  Top Layer w5: U2.45 -960.36,-193.64 v2(-954,-200)
  Bottom Layer w5: v2(-954,-200) -952.03,-198.03 -942.25,-198.03 -826.89,-82.67 U1.4
ISP_SDA: U1.3 U2.44 | length 356.6
  Top Layer w5: v2(-996.52,-214.61) -996.52,-212.36 -974.14,-189.97 U2.44
  Bottom Layer w6: v2(-996.52,-214.61) -993.15,-214.61 -983.25,-224.51 -857.93,-224.51 -835.74,-202.31 -835.74,-121.16 -826,-111.42 -798.24,-111.42 U1.3
LEDK: Q1.3 U1.11 | length 209.4
  Top Layer w6: Q1.3 -928.84,195 v2(-892,195)
  Bottom Layer w6: v2(-892,195) -892,164.97 -892,131.74 -884.42,124.16 -848.98,124.16 -835.07,110.24 U1.11
NetC7_1: C7.1 T1.1 U3.3 | length 331.6
  Top Layer w5: v2(-297.49,143.83) -296.81,144.51 C7.1@-296.81,164.16 ; C7.1 -290.23,158.24 -235,158.24 U3.3@-233.11,156.35
  Bottom Layer w5: v2@-297.49,143.47 T1.1@-154.02,0
  Bottom Layer w10.3: v2@-297.49,143.47 v2(-297.49,143.83) ; T1.1@-154.02,0 T1.1
NetC8_2: C8.2 U4.A2 | length 58.5
  Top Layer w6: U4.A2 -620.22,111.25 -614,117.47 C8.2@-614,166.26
NetC14_1: C14.1 U6.10 | length 55.6
  Top Layer w6: C14.1 -618.37,-244.73 U6.10
NetP1_1: P1.1 U4.A3 | length 272.8
  Top Layer w6: P1.1 -710.25,207.57 -605.69,207.57 -593.86,195.74 -593.86,116.99 U4.A3
NetP1_2: P1.2 U4.C3 | length 288
  Top Layer w7: P1.2 -602.26,252.33 -552.97,203.03 -552.97,88.37 -570.4,70.94 U4.C3@-596.6,70.94
NetQ1_1: Q1.1 R1.1 R2.1 | length 254.4
  Top Layer w5: Q1.1 -814.36,278.38 -811.91,275.93 -804.24,268.26 -804.24,223.64 -780.77,200.17 R1.1 R2.1
NetR4_2: R4.2 R5.2 U4.A1 | length 106.8
  Top Layer w6: R4.2 R5.2 -687.26,110.31 U4.A1
NetR6_2: R6.2 U4.C1 | length 73.2
  Top Layer w5: R6.2@-695.24,27.71 -693.08,27.71 -649.84,70.94 U4.C1
NetR7_2: R7.2 U4.B2 | length 88.4
  Top Layer w4: U4.B2 -610.72,81.13 -610.72,44.88 -619.4,36.2 -619.4,10.82 R7.2@-618.63,10.06
NetR8_2: R8.2 U4.B1 | length 62.5
  Top Layer w5: R8.2@-695.43,73.75 -678.55,90.63 U4.B1
NetR9_1: R9.1 U6.22 | length 94.4
  Top Layer w6: U6.22 -634.12,-61.74 -621.2,-48.83 -602.09,-48.83 -585.48,-32.22 -583.22,-32.22 R9.1
NetR10_1: R10.1 U5.5 | length 76.8
  Top Layer w8: R10.1 -302.67,-227.48 U5.5
NetR14_1: R14.1 U6.11 | length 67.6
  Top Layer w6: U6.11 -602.62,-206.08 -581.82,-226.87 -581.82,-237.09 -573.01,-245.9 R14.1
NetR15_1: R15.1 U6.9 | length 67.8
  Top Layer w5: R15.1 -666.28,-245.9 -656.97,-236.59 -656.97,-235.61 -634.03,-212.67 U6.9@-634.03,-192.42
PA0: U1.6 U2.39 | length 465.8
  Top Layer w5: v2(-1070.88,-233.85) -1070.88,-219.19 -1043.04,-191.34 U2.39
  Bottom Layer w5: v2(-1070.88,-233.85) -1011.01,-173.97 -936.6,-173.97 -885.26,-122.63 -885.26,-76.69 -836.11,-27.55 U1.6
PA3: U2.42
PA7: U2.4
PA8: P4.3 U2.5 | length 549.5
  Top Layer w5: P4.3 -1095.41,238.82 -1068.23,211.64 -990.53,211.64 -879.39,100.49 -879.39,66.44 -832.22,19.28 -832.22,-26.14 -879.77,-73.69 U2.5
PA9: P4.2 U2.6 | length 474.2
  Top Layer w5: v2(-1084,173) -1084,151.71 P4.2 ; v2(-984,159) -950.74,159 -888.39,96.65 -888.39,62.71 -841.22,15.55 -841.22,-22.41 -878.72,-59.91 U2.6
  Bottom Layer w5: v2(-1084,173) -1066.67,155.67 -991.39,155.67 -988.06,159 v2(-984,159)
PA12: U2.46
PA15: U2.43
PB2: U2.22
PB3: U2.21
PB4: P4.6 U2.20 | length 172.2
  Top Layer w5: v2(-1130.84,130.11) P4.6 ; v2(-1043.96,71.7) -1043.04,70.77 U2.20
  Bottom Layer w5: v2(-1130.84,130.11) -1102.89,130.11 -1044.48,71.7 v2(-1043.96,71.7)
PB5: U2.19
PB6: U2.18
PB7: U2.17
PB8: U2.8 U3.1 | length 1250.1
  Top Layer w5: v2(-1036.86,179.9) -1036.86,152.47 -1011.83,127.44 -944.64,127.44 -906.39,89.19 -906.39,55.26 -863.79,12.66 -863.79,-19.52 -876.62,-32.35 U2.8 ; v2(-265.01,228.08) -264.81,228.28 -228.82,228.28 U3.1
  Bottom Layer w5: v2(-1036.86,179.9) -1036.86,195.55 -998.87,233.54 -979.8,233.54 -923.48,289.86 -371.39,289.86 -309.6,228.08 v2(-265.01,228.08)
PB9: C6.1 U2.7 U3.5 | length 1468.7
  Top Layer w5: v2(-1008.62,190.21) -1008.62,145.35 -999.71,136.44 -940.91,136.44 -897.39,92.92 -897.39,58.98 -854.79,16.39 -854.79,-23.25 -877.67,-46.13 U2.7 ; U3.5 -132.2,193.01 C6.1 -82.3,200.53 v2(-82.3,213.07)
  Bottom Layer w5: v2(-1008.62,190.21) -1008.62,190.45 -918.21,280.86 -383.79,280.86 -294.78,191.85 -103.53,191.85 v2(-82.3,213.07)
PB10: U2.16
PB11: U2.15
PB14: P4.4 U2.12 | length 262.5
  Top Layer w5: P4.4 -1105.65,149.74 -1105.65,138.67 -1074.97,107.99 -953.61,107.99 -933.2,87.59 -933.2,32.58 U2.12
PB15: P4.5 U2.11 | length 375.9
  Top Layer w5: P4.5 -1119.03,239.33 -1061.29,181.59 -1061.29,140.45 -1037.84,116.99 -946.91,116.99 -919.02,89.1 U2.11
PB17: U2.9
PB23: P4.10 U2.25 | length 197.8
  Top Layer w6: P4.10 -1178.09,96.42 -1133.9,52.24 -1133.9,-0.06 -1129.17,-4.79 U2.25
VBAT: C10.2 P2.1 Q2.3 R11.1 U5.3 | length 630.5
  Top Layer w25: R11.1 -411.71,164.16 -411.41,164.45 -411.41,239.79 P2.1@-405.04,246.15 ; R11.1@-409.44,163.53 -368.44,122.53 -353.66,107.75 -338.26,107.75 -336.98,106.47 Q2.3 -294.24,104.5 -214.7,24.96 -214.7,-60.91 -145.73,-129.88 -145.73,-167.29 C10.2 -150.01,-163.01 -170.12,-163.01 -178.73,-154.4 U5.3
VBUS: C11.2 D2.1 P3.1 Q2.1 U5.4 | length 914.9
  Top Layer w30: Q2.1 -373.9,24.97 -373.16,24.22 -373.16,23.75 -359.89,10.48 C11.2@-359.89,-90.47 ; v3(-360.45,-121.79) v3@-359.56,-122.67 ; C11.2 v3@-359.56,-122.67 ; U5.4@-308.03,-152.58 -341.99,-152.58 -359.56,-135 v3@-359.56,-122.67
  Top Layer w40: v3(-85.12,-164.57) v3@-84.4,-163.85 ; v3@-48.92,-163.85 v3(-49.65,-163.85) ; v3@-84.4,-163.85 -69.81,-149.26 P3.1 -54.37,-103.57 -54.37,-120.77 -53.99,-121.15 -53.99,-159.5 v3(-49.65,-163.85) ; v3@-84.4,-163.85 v3(-49.65,-163.85)
  Layer 2 w30: v3(-360.45,-121.79) -303.02,-121.79 -285.67,-139.13
  Layer 2 w40: v3@-355.65,-119.76 -359.15,-116.26 v3(-359.15,-64.88) -260.19,-163.85 v3(-49.65,-163.85)
VDCIA: C2.1 L1.2 U2.35 | length 718.4
  Top Layer w8: C2.1 -1181.7,-217.44 -1155.72,-191.46 -1111.56,-191.46 -1110.87,-190.77 -1109.89,-190.77 -1098.15,-179.03 U2.35
  Top Layer w20: v3(-1182.02,-243.64) -1181.86,-243.48 -1181.86,-218.59 C2.1 ; L1.2@-775.39,-275.38 -770.31,-270.3 -770.31,-256.81 -769.09,-255.58 -768.9,-255.77 v3(-768.9,-255.91)
  Layer 2 w20: v3(-1182.02,-243.64) -1180.49,-242.11 -1180.49,-198.77 -1131.07,-149.36 -815.96,-149.36 -768.9,-196.42 v3(-768.9,-255.91)
VDCID: C4.2 L1.1 L2.2 U2.1 | length 268.2
  Top Layer w7: U2.1 U2.1@-895.23,-128.81 ; C4.2@-843.81,-128.81 U2.1@-895.23,-128.81 ; -826.97,-135.19 -827.45,-134.71 -889.32,-134.71 U2.1@-895.23,-128.81
  Top Layer w20: C4.2 -826.97,-135.19 -810.14,-135.19 -789.2,-156.13 L2.2@-776.24,-156.13
  Top Layer w30: L1.1@-776.85,-211.37 -776.24,-210.76 L2.2@-776.24,-156.13
VINTA: C1.1 U2.33 | length 83
  Top Layer w5: C1.1@-1182.34,-94.62 -1180.23,-96.74 -1160.05,-96.74 -1141.76,-115.03 U2.33
VSW: L2.1 U2.2 | length 254.4
  Top Layer w7: U2.2 -871.65,-115.03 ; L2.1@-791.59,-83.06 -831.62,-83.06 -863.58,-115.03 -871.65,-115.03 ; L2.1@-763.88,-77.5 -834.12,-77.5 -871.65,-115.03
X32KI: U2.48 Y2.1 | length 116.4
  Top Layer w5: U2.48 -918.62,-166.17 -918.62,-182.62 Y2.1
X32KO: U2.47 Y2.2 | length 110.6
  Top Layer w5: Y2.2@-961.56,-247.95 -955.24,-254.27 -948.72,-254.27 -948.72,-233.79 -932.8,-217.87 U2.47
X32MI: U2.32 Y1.1 | length 145.8
  Top Layer w6: Y1.1@-1229.43,-42.92 -1220.78,-42.92 -1196.37,-67.33 -1167.93,-67.33 -1134.22,-101.04 -1107.96,-101.04 U2.32
X32MO: U2.31 Y1.3 | length 128.5
  Top Layer w6: Y1.3@-1174.08,1.67 -1174.08,0.18 -1146.4,-27.5 -1146.4,-69.06 -1128.2,-87.26 -1107.96,-87.26 U2.31
pads on no net: P4.11 U1.1 U1.2 U1.9 U2.27 U2.28 U2.29 U2.30 U3.4 U3.6 U6.2 U6.3 U6.4 U6.5 U6.6 U6.7 U6.14 U6.15 U6.16 U6.17 U6.19 U6.21

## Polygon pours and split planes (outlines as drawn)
GND on Top Layer "GND" (hatched Horizontal grid 8 track 8, remove dead copper, pour order 1): -1555.12,305.12 -1555.12,-305.12 0,-305.12 0,305.12 -246.84,305.12
GND on Top Layer "GND1" (hatched Horizontal grid 8 track 8, remove dead copper, pour order 2): -1276.09,-106.31 -1081.47,-106.31 -1081.47,-199.5 -1276.09,-199.5
GND on Layer 1 "GND" (hatched Horizontal grid 8 track 8, remove dead copper, pour order 0): -1555.12,305.12 0,305.12 0,-305.12 -1555.12,-305.12 -1555.12,137.79
GND on Layer 2 "GND" (hatched Horizontal grid 8 track 8, remove dead copper, pour order 4): -1554.56,306.16 -1554.56,-305.1 0,-305.1 0,305.12 -265.75,305.12
GND on Bottom Layer "GND" (hatched Horizontal grid 8 track 8, remove dead copper, pour order 3): -1555.12,305.12 -1555.12,-305.12 0,-305.12 0,304.78 -304.48,304.78

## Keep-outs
Keep-Out Layer:
  lines w10: -381.89,-305.12 -381.89,-260.71 -322.83,-260.71 -322.83,-305.12 ; -381.89,-305.12 -381.89,-305.12 ; -381.89,-305.12 -1313.78,-305.12 -1313.78,-260.71 -1366.14,-260.71 -1366.14,-305.12 -1384.27,-305.12 cw(c-1386.03,-136.03) -1555.12,-137.8 -1555.12,-43.7 -1409.98,-43.7 -1409.98,45.28 -1555.12,45.28 -1555.12,137.79 cw(c-1386.03,136.03) -1384.27,305.12 -1365.35,305.12 -1365.35,267.34 -1313.39,267.34 -1313.39,305.12 -303.54,305.12 -303.54,267.34 -265.75,267.34 -265.75,305.12 -246.84,305.12 cw(c-232.1,31.48) 0,177.17 ; -322.82,-305.1 -246.84,-305.1 ccw(c-233.88,-28.03) 0,-177.15 0,177.16 ; -322.83,-305.12 -322.82,-305.1 ; 0,177.16 0,177.17

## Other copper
Top Layer:
  rectangle net GND: -554.94,223.5 -457.49,291.69
  rectangle net GND: -1285.99,-185.51 -1240.51,-173.7
  rectangle net GND: -1280.09,-216.23 -1255.27,-173.7
  pour cut-out: -812.11,-62.46 -734.36,-62.46 -734.36,-172.81 -811.79,-172.81
Layer 1:
  rectangle net GND: -657.92,-170.3 -592.6,-91.32
  rectangle net GND: -1086.58,-144.3 -938.57,8.73
Bottom Layer:
  rectangle net GND: -1084.58,-134.28 -947.2,5.22
Multi-Layer:
  pour cut-out: -312.8,125.63 -312.8,176.73 -119.74,176.73 -119.74,126.09
  pour cut-out: 64.57,0 cw(c-112.59,0) -112.59,-177.17 cw(c-112.59,0) -289.76,0 cw(c-112.59,0) -112.59,177.17 cw(c-112.59,0)
  pour cut-out: -1555.12,-305.12 -1276.09,-305.12 -1276.09,305.12 -1555.12,305.12

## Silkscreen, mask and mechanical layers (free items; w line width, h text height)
Bottom Overlay:
  text "wristband-1v1" at -639.44,-293.67 h35 r359.82
Mechanical 1:
  lines w10: -1555.12,-137.8 ccw(c-1386.04,-136.02) -1384.27,-305.1 -1366.14,-305.12 -1366.14,-260.71 -1313.78,-260.71 -1313.78,-305.12 -381.89,-305.12 -381.89,-260.71 -322.83,-260.71 -322.83,-305.12 -246.85,-305.12 ccw(c-233.14,-29.47) 0,-177.15 0,177.17 ccw(c-233.14,29.48) -246.84,305.12 -265.75,305.12 -265.75,267.34 -303.54,267.34 -303.54,305.12 -1120.3,305.12 -1313.39,305.12 -1313.39,267.34 -1365.35,267.34 -1365.35,305.12 -1384.27,305.12 ccw(c-1386.03,136.03) -1555.12,137.8 -1555.12,45.28 -1409.98,45.28 -1409.98,-43.7 -1555.12,-43.7 -1555.12,-137.8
